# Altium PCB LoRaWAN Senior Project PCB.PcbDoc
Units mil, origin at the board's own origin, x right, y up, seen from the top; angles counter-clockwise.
Board outline 5000 x 2500 mil, 2 copper layers (Top Layer, Bottom Layer); 30 components, 27 nets, 105 pads, 2 vias.
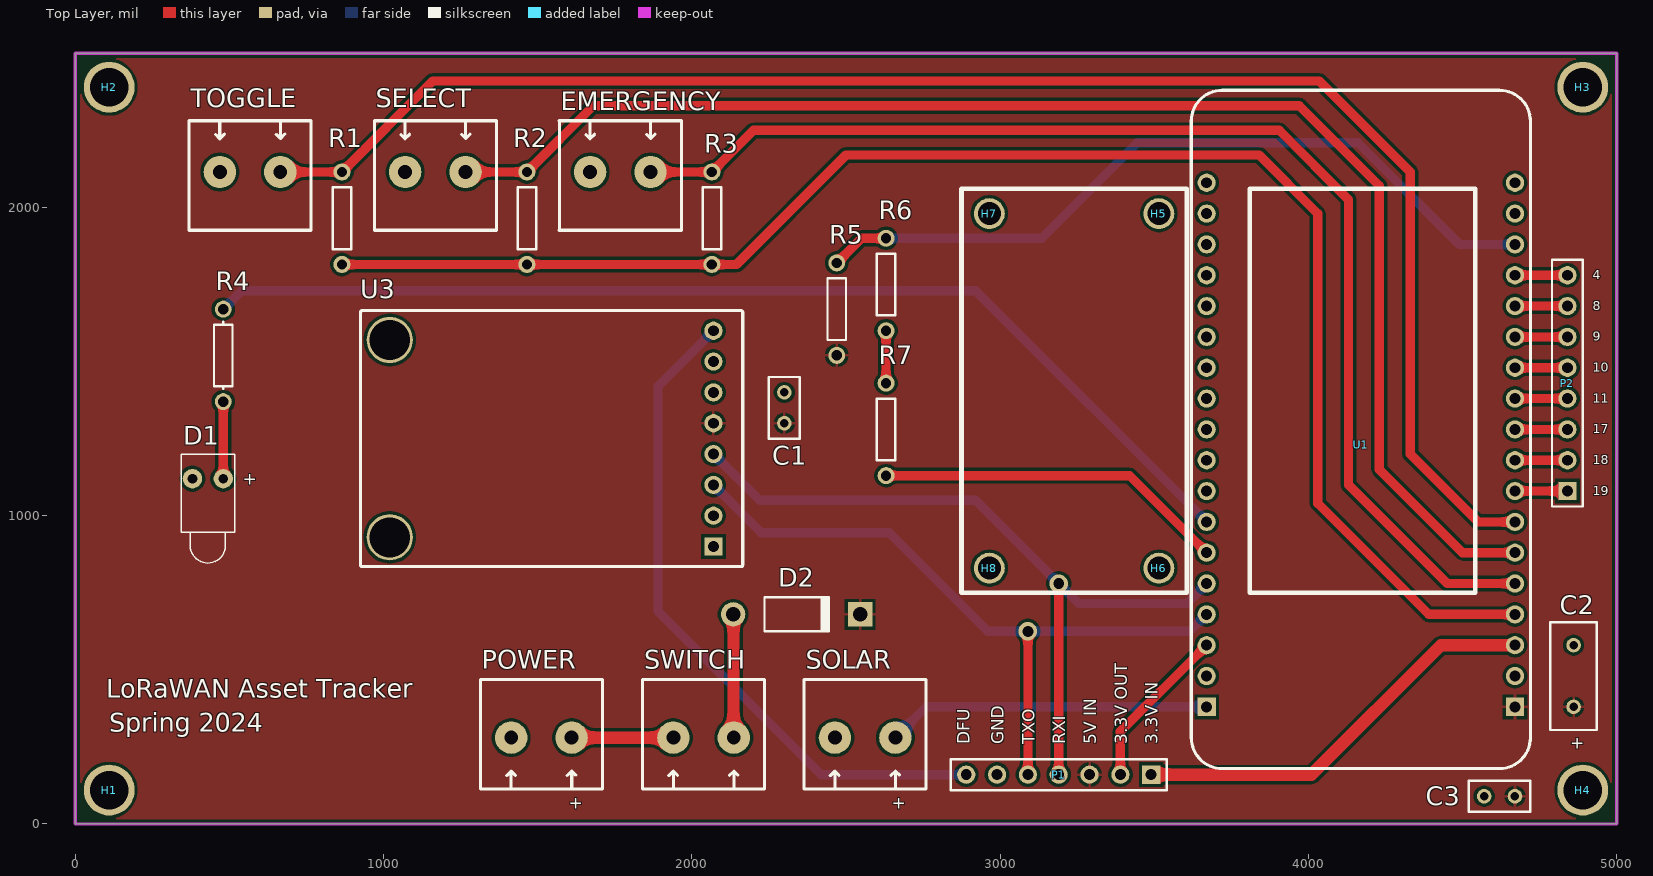
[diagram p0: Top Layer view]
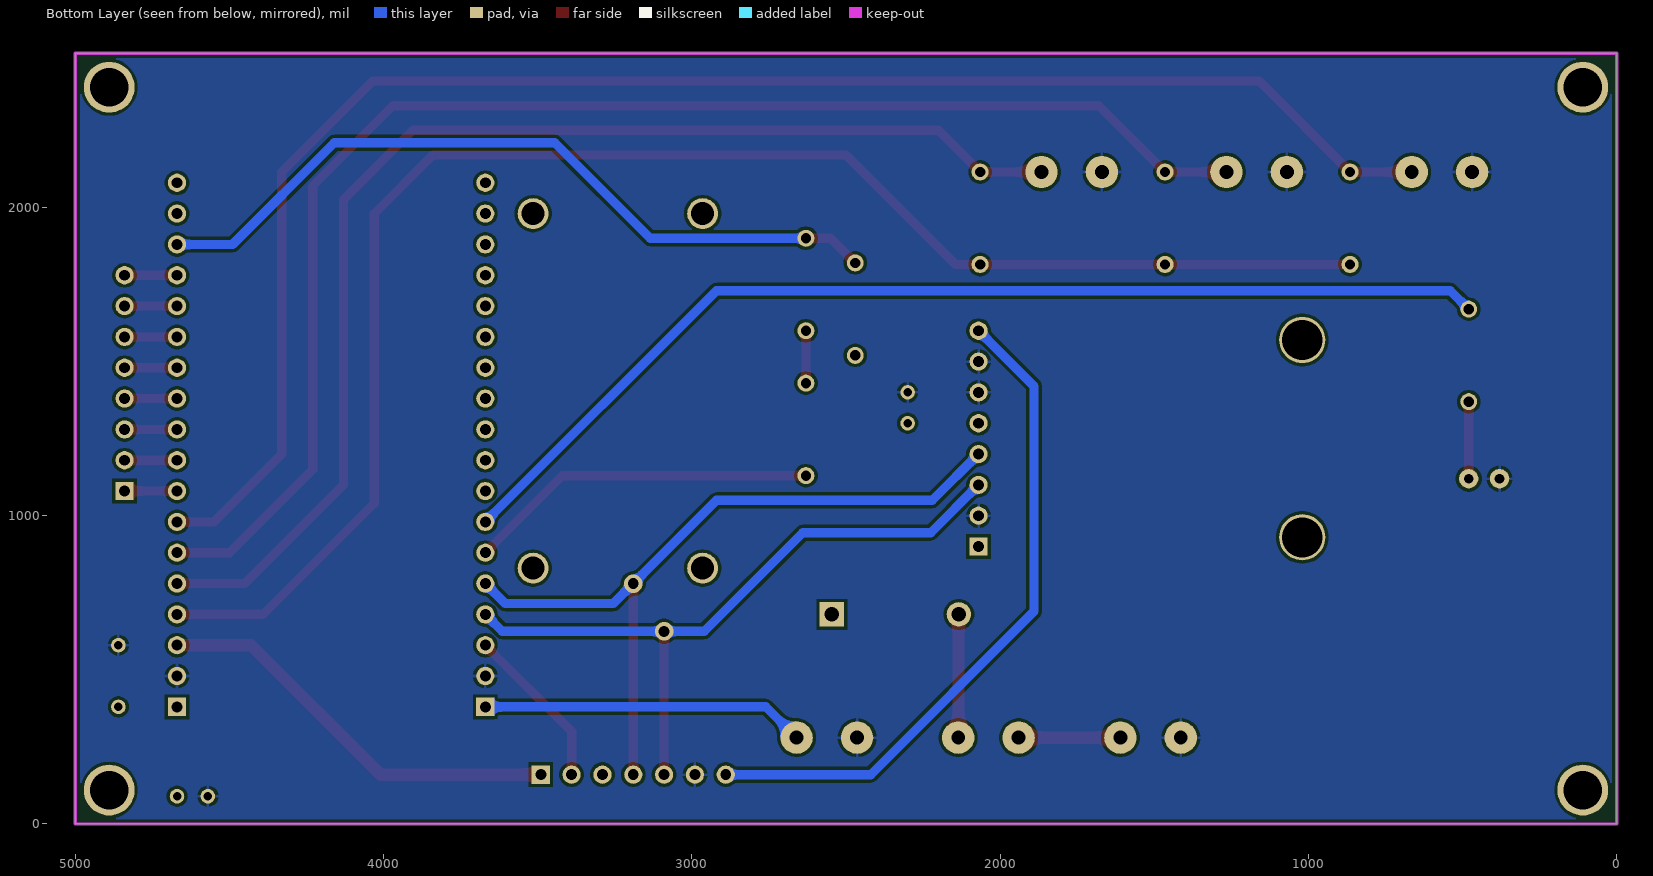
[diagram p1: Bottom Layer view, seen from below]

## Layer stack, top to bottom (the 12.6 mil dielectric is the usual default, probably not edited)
Top Solder: solder mask 0.4, Solder Resist, Dk 3.5
Top Layer: signal copper 1.4
Dielectric 1: dielectric 12.6, FR-4, Dk 4.8
Bottom Layer: signal copper 1.4
Bottom Solder: solder mask 0.4, Solder Resist, Dk 3.5

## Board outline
0,0 0,2500 5000,2500 5000,0

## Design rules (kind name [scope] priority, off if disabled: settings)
Clearance [All] p1: gap=10 ignorepadtopadclearanceinfootprint=FALSE except(0: Arc-Hole Track-Hole SMDPad-Hole THPad-Hole Via-Hole Fill-Hole Poly-Hole Region-Hole Text-Hole)
PolygonConnect [All] p1: connectstyle=Relief reliefconductorwidth=10 reliefentries=4 polygonreliefangle="90 Angle" airgapwidth=10
RoutingVias [All] p1: holewidth=28 width=50 viastyle="Through Hole" minholewidth=28 minwidth=50 maxholewidth=36 maxwidth=60
SolderMaskExpansion [All] p1: expansion=4 istentingtop=FALSE
Width [All] p1: maxlimit=50 minlimit=10 preferedwidth=20 minimp=50.000000 maximp=50.000000 favimp=50.000000
30 further rules are at their usual default settings.

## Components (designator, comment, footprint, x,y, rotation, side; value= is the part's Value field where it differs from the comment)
C1 "Cap" RAD-0.1 2300,1350 r270 top value=100nF
C2 "Cap Pol1" RAD-0.2 4860,480 r90 top value=100uF
C3 "Cap" RAD-0.1 4620,90 r0 top value=100nF
D1 "LED1" LED-1 430,1120 r270 top
D2 "Diode 1N5819" DO-41 2340,680 r0 top
EMERGENCY "Button Port" CON2screw 1866,2115 r180 top
H1 "Hole 125mil" "Hole 125mil" 110,110 r0 top
H2 "Hole 125mil" "Hole 125mil" 110,2390 r0 top
H3 "Hole 125mil" "Hole 125mil" 4890,2390 r0 top
H4 "Hole 125mil" "Hole 125mil" 4890,110 r0 top
H5 "Hole 3mm" "Hole 3mm" 3905,1805 r0 top
H6 "Hole 3mm" "Hole 3mm" 3905,655 r0 top
H7 "Hole 3mm" "Hole 3mm" 3355,1805 r0 top
H8 "Hole 3mm" "Hole 3mm" 3355,655 r0 top
P1 "Debug Headers" HDR1X7 3490,160 r180 top
P2 "Header 8" HDR1X8 4840,1080 r90 top
POWER "Power Port" CON2screw 1414,280 r0 top
R1 "Res1" RESISTOR 865,1965 r90 top value=1k
R2 "Res1" RESISTOR 1465,1965 r90 top value=1k
R3 "Res1" RESISTOR 2065,1965 r90 top value=1k
R4 "Res1" AXIAL-0.3 480,1520 r90 top value=1K
R5 "Res1" RESISTOR 2470,1670 r270 top value=10k
R6 "Res1" RESISTOR 2630,1750 r90 top value=4.7k
R7 "Res1" RESISTOR 2630,1280 r90 top value=3k
SELECT "Button Port" CON2screw 1266,2115 r180 top
SOLAR "Solar Port" CON2screw 2464,280 r0 top
SWITCH "Switch Port" CON2screw 1940,280 r0 top
TOGGLE "Button Port" CON2screw 665,2115 r180 top
U1 "Heltec Dev-Board" HELTEC 4670,380 r180 top
U3 "BLE" "ADAFRUIT BLE" 2065,885 r90 top

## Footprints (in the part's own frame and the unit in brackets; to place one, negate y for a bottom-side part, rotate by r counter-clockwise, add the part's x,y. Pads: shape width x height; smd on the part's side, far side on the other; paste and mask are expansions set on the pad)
"ADAFRUIT BLE" [mm]
  rect 1.5x1.5 hole 0.9: 1(0.381,-0.127)
  round 1.5 hole 0.9: 2(2.921,-0.127) 3(5.461,-0.127) 4(8.001,-0.127) 5(10.541,-0.127) 6(13.081,-0.127) 7(15.621,-0.127) 8(18.161,-0.127)
  round 3.81 hole 3.302: ""(1.143,26.543) ""(17.399,26.543)
  silkscreen extent -1.27,-2.54 19.81,28.96
AXIAL-0.3 [mm] "Axial Device, Thru-Hole; 2 Leads; 0.3 in Pin Spacing"
  round 1.4 hole 0.85: 1(-3.81,0) 2(3.81,0)
  silkscreen extent -2.77,-0.76 2.77,0.76
CON2screw [mil]
  round 105 hole 45: 1(0,0) 2(196,0)
  silkscreen extent -100,-166 296,189
DO-41 [mm] "Diode, Axial; Body 5.2 x 2.7 mm (LxDia. max), Lead Dia. 0.86 mm (max)"
  round 2 hole 1.2: 1(-5.23,0)
  rect 2x2 hole 1.2: 2(5.23,0)
  silkscreen extent -2.65,-1.4 2.75,1.4
HDR1X7 [mm] "Connector; Header; 7 Position"
  rect 1.5x1.5 hole 0.9: 1(0,0)
  round 1.5 hole 0.9: 2(2.54,0) 3(5.08,0) 4(7.62,0) 5(10.16,0) 6(12.7,0) 7(15.24,0)
  silkscreen extent -1.27,-1.27 16.51,1.27
HDR1X8 [mm] "Connector; Header; 8 Position"
  rect 1.5x1.5 hole 0.9: 1(0,0)
  round 1.5 hole 0.9: 2(2.54,0) 3(5.08,0) 4(7.62,0) 5(10.16,0) 6(12.7,0) 7(15.24,0) 8(17.78,0)
  silkscreen extent -1.27,-1.27 19.05,1.27
HELTEC [mm]
  rect 1.5x1.5 hole 0.9: 1(25.4,0) 36(0,0)
  round 1.5 hole 0.9: 2(25.4,-2.54) 3(25.4,-5.08) 4(25.4,-7.62) 5(25.4,-10.16) 6(25.4,-12.7) 7(25.4,-15.24) 8(25.4,-17.78) 9(25.4,-20.32) 10(25.4,-22.86) 11(25.4,-25.4) 12(25.4,-27.94) 13(25.4,-30.48) 14(25.4,-33.02) 15(25.4,-35.56) 16(25.4,-38.1) 17(25.4,-40.64) 18(25.4,-43.18) 19(0,-43.18) 20(0,-40.64) 21(0,-38.1) 22(0,-35.56) 23(0,-33.02) 24(0,-30.48) 25(0,-27.94) 26(0,-25.4) 27(0,-22.86) 28(0,-20.32) 29(0,-17.78) 30(0,-15.24) 31(0,-12.7) 32(0,-10.16) 33(0,-7.62) 34(0,-5.08) 35(0,-2.54)
  silkscreen extent -1.27,-50.8 26.67,5.08
"Hole 3mm" [mil]
  round 100 hole 75: 1(-390,175)
"Hole 125mil" [mil]
  round 165 hole 125: 1(0,0)
LED-1 [mm] "LED; 2 Leads"
  round 1.6 hole 0.8: 1(0,1.27) 2(0,-1.27)
  silkscreen extent -2,-2.2 6.95,2.2
RAD-0.1 [mm] "Radial Cap, Thru-Hole; 2 Leads; 0.1 in Pin Spacing"
  round 1.2 hole 0.7: 1(-1.27,0) 2(1.27,0)
  silkscreen extent -2.54,-1.27 2.54,1.27
RAD-0.2 [mm] "Radial Cap, Thru-Hole; 2 Leads; 0.2 in Pin Spacing"
  round 1.2 hole 0.7: 1(-2.54,0) 2(2.54,0)
  silkscreen extent -4.44,-1.91 4.44,1.91
RESISTOR [mm]
  round 1.4 hole 0.85: 1(-3.81,0) 2(3.81,0)
  silkscreen extent -2.54,-0.76 2.54,0.76

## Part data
C1 C3: "Capacitor"
C2: "Polarized Capacitor (Radial)"
D1: "Typical RED GaAs LED"
D2: library part "Diode 1N4001", "1 Amp General Purpose Rectifier"
EMERGENCY POWER SELECT SOLAR SWITCH TOGGLE: library part Power
P1: library part "Header 7", "Header, 7-Pin"
P2: "Header, 8-Pin"
R1 R2 R3 R4 R5 R6 R7: "Resistor"
U3: library part "Adafruit BLE"

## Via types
v1: diameter 60, hole 35.43, Top Layer to Bottom Layer, 2 vias

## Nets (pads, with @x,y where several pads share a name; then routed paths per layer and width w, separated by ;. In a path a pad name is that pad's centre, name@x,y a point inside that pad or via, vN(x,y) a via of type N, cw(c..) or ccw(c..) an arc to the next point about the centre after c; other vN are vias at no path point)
3.3V_INPUT: P1.1 U1.34 | length 1354
  Top Layer w40: P1.1 4010,160 4430,580 U1.34
3.3V_OUTPUT: P1.2 U1.3 | length 536
  Top Layer w30: P1.2 3390,300 U1.3
5V_INPUT: C1.2 C2.1 C3.2 D2.2 P1.3 R5.2 U1.36 U3.5
B_POW: R1.1 R2.1 R3.1 U1.33 | length 5119.9
  Top Layer w30: R1.1 R2.1 R3.1 2145,1815 2500,2170 3840,2170 4030,1980 4030,1040 4390,680 U1.33
DFU: P1.7 U3.8 | length 2204.1
  Bottom Layer w30: U3.8 1890,1420 1890,690 2420,160 P1.7
EMERGENCY_BUTTON: EMERGENCY.1 R3.2 U1.32 | length 4010.7
  Top Layer w30: EMERGENCY.1 R3.2 2200,2250 3905,2250 4130,2025 4130,1100 4450,780 U1.32
GND: C1.1 C2.2 C3.1 D1.2 EMERGENCY.2 P1.6 POWER.1 SELECT.2 SOLAR.1 TOGGLE.2 U1.2 U1.35 U3.2 U3.6 U3.7
LED: R4.2 U1.7 | length 3525.5
  Bottom Layer w30: R4.2 540,1730 2920,1730 U1.7
NetD1_1: D1.1 R4.1 | length 250
  Top Layer w30: D1.1 R4.1
NetD2_1: D2.1 SWITCH.2 | length 401.5
  Top Layer w30: D2.1@2133.59,679.5 D2.1
  Top Layer w40: D2.1 2135.05,679.05 2135.05,280.95 SWITCH.2
NetP2_1: P2.1 U1.29 | length 170
  Top Layer w30: U1.29 P2.1
NetP2_2: P2.2 U1.28 | length 170
  Top Layer w30: U1.28 P2.2
NetP2_3: P2.3 U1.27 | length 170
  Top Layer w30: U1.27 P2.3
NetP2_4: P2.4 U1.26 | length 170
  Top Layer w30: U1.26 P2.4
NetP2_5: P2.5 U1.25 | length 170
  Top Layer w30: U1.25 P2.5
NetP2_6: P2.6 U1.24 | length 170
  Top Layer w30: U1.24 P2.6
NetP2_7: P2.7 U1.23 | length 170
  Top Layer w30: U1.23 P2.7
NetP2_8: P2.8 U1.22 | length 170
  Top Layer w30: U1.22 P2.8
NetPOWER_2: POWER.2 SWITCH.1 | length 330
  Top Layer w40: POWER.2 SWITCH.1
NetR6_1: R6.1 R7.2 | length 170
  Top Layer w30: R7.2 R6.1
RXI: P1.4 U1.5 U3.4 | length 2447.8
  Top Layer w30: P1.4 v1(3190,780)
  Bottom Layer w30: U3.4 2220,1050 2920,1050 v1(3190,780) 3255,715 3605,715 U1.5
Select_Button: R2.2 SELECT.1 U1.31 | length 4632.6
  Top Layer w30: SELECT.1 R2.2 1680,2330 3970,2330 4230,2070 4230,1150 4500,880 U1.31
SOLAR_INPUT: SOLAR.2 U1.1 | length 1051.4
  Bottom Layer w30: SOLAR.2 2760,380 U1.1
Toggle_Button: R1.2 TOGGLE.1 U1.30 | length 5255.5
  Top Layer w30: TOGGLE.1 R1.2 1160,2410 4035,2410 4330,2115 4330,1200 4550,980 U1.30
TXO: P1.5 U1.4 U3.3 | length 2284.5
  Top Layer w30: P1.5 v1(3090,625)
  Bottom Layer w30: U3.3 2225,945 2640,945 2960,625 v1(3090,625) 3615,625 U1.4
VBAT_ADC: R5.1 R6.2 U1.21 | length 2498.2
  Top Layer w30: R5.1 2550,1900 R6.2
  Bottom Layer w30: R6.2 3135,1900 3445,2210 4160,2210 4490,1880 U1.21
VBAT_GND: R7.1 U1.6 | length 1143.6
  Top Layer w30: R7.1 3420,1130 U1.6
pads on no net: H1.1 H2.1 H3.1 H4.1 H5.1 H6.1 H7.1 H8.1 U1.8 U1.9 U1.10 U1.11 U1.12 U1.13 U1.14 U1.15 U1.16 U1.17 U1.18 U1.19 U1.20 U3. U3.1

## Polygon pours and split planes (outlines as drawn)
5V_INPUT on Top Layer "NONET_L-01_P-001" (solid, pour order 1): 0,2500 5000,2500 5000,0 0,0
GND on Bottom Layer "NONET_L-01_P-001" (solid, pour order 0): 0,2500 5000,2500 5000,0 0,0

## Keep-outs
Keep-Out Layer:
  the board outline again, w10

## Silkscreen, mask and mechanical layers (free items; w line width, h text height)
Top Overlay:
  lines w15: 2874.5,750 3605.5,750 3605.5,2060 2874.5,2060 2874.5,750 ; 3810,750 4541,750 4541,2060 3810,2060 3810,750
  text "4" at 4922,1767 h30
  text "8" at 4922,1667 h30
  text "9" at 4922,1567 h30
  text "10" at 4922,1467 h30
  text "11" at 4922,1367 h30
  text "17" at 4922,1267 h30
  text "18" at 4922,1167 h30
  text "+" at 543.66,1099.94 h40
  text "19" at 4922,1067 h30
  text "LoRaWAN Asset Tracker" at 100,410 h60
  text "Spring 2024" at 110,299.99 h60
  text "DFU" at 2902,258 h40 r90
  text "GND" at 3012,258 h40 r90
  text "TXO" at 3112,258 h40 r90
  text "RXI" at 3212,258 h40 r90
  text "5V IN" at 3312,258 h40 r90
  text "3.3V OUT" at 3412,258 h40 r90
  text "3.3V IN" at 3512,258 h40 r90
  text "+" at 4850,243.34 h40
  text "+" at 1600,50 h40
  text "+" at 2648.66,49.94 h40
